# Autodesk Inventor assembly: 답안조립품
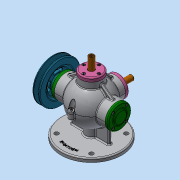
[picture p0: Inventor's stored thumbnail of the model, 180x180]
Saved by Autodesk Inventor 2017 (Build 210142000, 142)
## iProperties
Part Number: 답안조립품
Material: 일반
Document SubType Name: Assembly
Designer: MRC
Author: MRC
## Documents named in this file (17)
- C:\Users\MRC\Desktop\620909V1004_\620909V1004\답안조립품.iam
- C:\Users\MRC\Desktop\620909V1004_\620909V1004\본체.ipt
- C:\Users\MRC\Desktop\620909V1004_\620909V1004\V-벨트풀리.ipt
- C:\Users\MRC\Desktop\620909V1004_\620909V1004\너트-M8x1.ipt
- C:\Users\MRC\Desktop\620909V1004_\620909V1004\뒤커버.ipt
- C:\Users\MRC\Desktop\620909V1004_\620909V1004\베어링- 6202.ipt
- C:\Users\MRC\Desktop\620909V1004_\620909V1004\본체커버.ipt
- C:\Users\MRC\Desktop\620909V1004_\620909V1004\볼트 M4x0.7.ipt
- C:\Users\MRC\Desktop\620909V1004_\620909V1004\슬라이드 커버.ipt
- C:\Users\MRC\Desktop\620909V1004_\620909V1004\슬라이드.ipt
- C:\Users\MRC\Desktop\620909V1004_\620909V1004\앞커버.ipt
- C:\Users\MRC\Desktop\620909V1004_\620909V1004\오일실.ipt
- C:\Users\MRC\Desktop\620909V1004_\620909V1004\와셔 8x17.ipt
- C:\Users\MRC\Desktop\620909V1004_\620909V1004\축.ipt
- C:\Users\MRC\Desktop\620909V1004_\620909V1004\키-4x4.ipt
- C:\Users\MRC\Desktop\620909V1004_\620909V1004\가변스프링1.ipt
- C:\Users\MRC\Desktop\620909V1004_\620909V1004\가변스프링2.ipt
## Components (20 placed, 4 different names)
1. V-벨트풀리:1
2. M4x0.7x12:1
3. M4x0.7x12:2
4. M4x0.7x12:3
5. M4x0.7x12:4
6. M4x0.7x12:5
7. M4x0.7x12:6
8. M4x0.7x12:7
9. M4x0.7x12:8
10. M4x0.7x12:9
11. M4x0.7x12:10
12. M4x0.7x12:11
13. M4x0.7x12:12
14. M4x0.7x12:13
15. M4x0.7x12:14
16. M4x0.7x12:15
17. M4x0.7x12:16
18. M4x0.7x12:17
19. 가변스프링1:1
20. 가변스프링2:1
